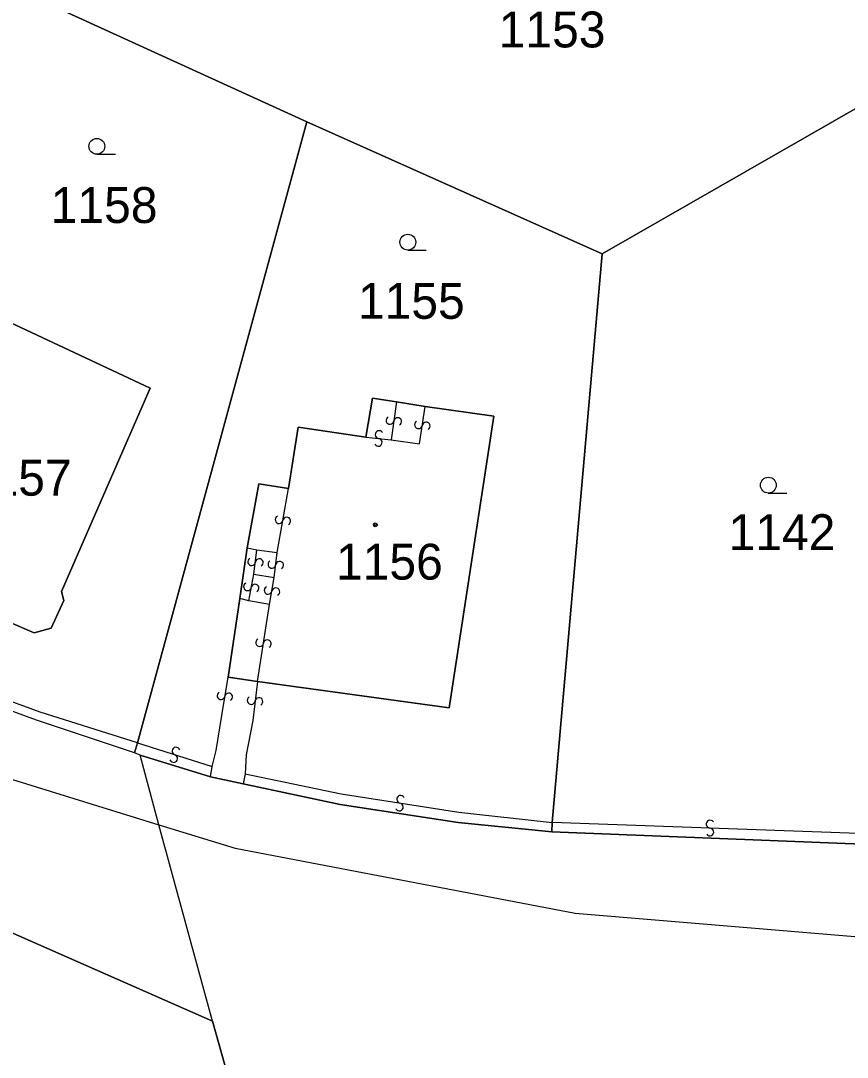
# Model space of a CAD drawing. Extents: x -600309 to -598967, y -1161267 to -1160292.
# Drawn here: x -599956.99 to -599917.86, y -1160621.06 to -1160571.95 of the extents above; entities that cross this region are included whole.
import ezdxf

# ---------------------------------------------------------------- set-up
doc = ezdxf.new("R2010")
doc.units = 0
for name, color, linetype in [('Level 1', 7, 'Continuous'), ('Level 13', 7, 'Continuous'), ('Level 3', 7, 'Continuous'), ('Level 4', 7, 'Continuous'), ('Level 5', 7, 'Continuous'), ('Level 60', 7, 'Continuous'), ('Vrstva 60', 7, 'Continuous')]:
    doc.layers.add(name, color=color, linetype=linetype)

msp = doc.modelspace()

# ---------------------------------------------------------------- linework, layer by layer
at = {"layer": 'Level 1'}
for points in [[(-599947.92, -1160619.35), (-599967.59, -1160610.68), (-599967.72, -1160610.62), (-599986.75, -1160601.72), (-600000.45, -1160595.4), (-600016.14, -1160587.57), (-600029.82, -1160579.77), (-600047.03, -1160569.17)], [(-599943.45, -1160576.74), (-599956.77, -1160570.64)], [(-599929.47, -1160582.99), (-599910.35, -1160572.03)], [(-599951.47, -1160606.16), (-599943.45, -1160576.74)], [(-599929.47, -1160582.99), (-599943.45, -1160576.74)], [(-599931.84, -1160609.93), (-599929.47, -1160582.99)], [(-599964.88, -1160596.05), (-599964.47, -1160595.25), (-599964, -1160595.17), (-599962.35, -1160591.23), (-599962.87, -1160591), (-599961.13, -1160587.24), (-599960.62, -1160587.42), (-599959.57, -1160585.28), (-599950.87, -1160589.35), (-599955.07, -1160598.99), (-599954.95, -1160599.42), (-599955.55, -1160600.73), (-599956.36, -1160600.95), (-599957.61, -1160600.42), (-599957.75, -1160599.84), (-599962.84, -1160597.43), (-599963.36, -1160597.66), (-599964.53, -1160597.13), (-599964.88, -1160596.05)], [(-599937.85, -1160590.23), (-599934.59, -1160590.69), (-599936.71, -1160604.5), (-599945.78, -1160603.26)], [(-599940.65, -1160591.67), (-599940.34, -1160589.83), (-599939.2, -1160590.01)], [(-599939.2, -1160590.01), (-599937.85, -1160590.23)], [(-599944.32, -1160594.11), (-599943.86, -1160591.21), (-599940.65, -1160591.67)], [(-599946.27, -1160596.92), (-599945.72, -1160593.89), (-599944.32, -1160594.11)], [(-599946.62, -1160599.32), (-599946.27, -1160596.92)], [(-599951.61, -1160606.63), (-599956.25, -1160605.09), (-599963.19, -1160602.54), (-599967.54, -1160600.81), (-599970.27, -1160599.54)], [(-599947.18, -1160603.05), (-599946.62, -1160599.32)], [(-599945.78, -1160603.26), (-599947.18, -1160603.05)], [(-599951.61, -1160606.63), (-599951.47, -1160606.16)], [(-599951.34, -1160606.74), (-599951.61, -1160606.63)], [(-599948.01, -1160607.77), (-599951.34, -1160606.74)], [(-599950.45, -1160610.04), (-599951.34, -1160606.74)], [(-599946.46, -1160608.11), (-599948.01, -1160607.77)], [(-599931.85, -1160610.38), (-599936.28, -1160609.94), (-599941.87, -1160609.09), (-599946.46, -1160608.11)], [(-599947.92, -1160619.35), (-599950.45, -1160610.04)], [(-599931.85, -1160610.38), (-599931.84, -1160609.93)], [(-599916.36, -1160611), (-599931.85, -1160610.38)], [(-599945.69, -1160627.27), (-599947.92, -1160619.35), (-599967.59, -1160610.68)], [(-599822.46, -1160624.97), (-599824.85, -1160625.23), (-599827.9, -1160625.24), (-599856.9, -1160625.7), (-599897.68, -1160626.45), (-599908.66, -1160626.66), (-599911.59, -1160626.72), (-599913.75, -1160626.78), (-599917.47, -1160626.86), (-599931.02, -1160627.04), (-599938.13, -1160627.17), (-599938.52, -1160627.22), (-599945.69, -1160627.27), (-599947.92, -1160619.35)]]:
    msp.add_lwpolyline(points, dxfattribs=at)
at = {"layer": 'Level 13'}
for centre, start, end in [((-599939.512, -1160590.883), 118.9391, 351.5291), ((-599939.148, -1160590.938), 299.1535, 171.2515), ((-599938.162, -1160591.091), 118.6996, 350.7976), ((-599937.798, -1160591.149), 298.4851, 171.0751), ((-599940.027, -1160591.557), 30.6629, 262.7609), ((-599940.072, -1160591.923), 210.4484, 83.0384), ((-599944.761, -1160595.587), 117.4511, 349.5491), ((-599944.399, -1160595.653), 297.2366, 169.8266), ((-599946.063, -1160597.574), 119.9413, 352.0393), ((-599945.698, -1160597.625), 299.7269, 172.3169), ((-599945.103, -1160597.707), 120.6066, 352.7046), ((-599944.737, -1160597.752), 300.3921, 172.9821), ((-599946.261, -1160598.764), 116.6714, 348.7694), ((-599945.899, -1160598.835), 296.4569, 169.0469), ((-599945.281, -1160598.936), 117.2634, 349.3614), ((-599944.919, -1160599.003), 297.049, 169.639), ((-599945.682, -1160601.41), 118.6502, 350.7482), ((-599945.318, -1160601.469), 298.4357, 171.0257), ((-599947.512, -1160603.928), 118.0125, 350.1105), ((-599947.149, -1160603.991), 297.7981, 170.3881), ((-599946.083, -1160604.156), 120.0333, 352.6233), ((-599945.717, -1160604.205), 300.2477, 172.3457), ((-599949.642, -1160606.555), 19.6692, 251.7672), ((-599949.757, -1160606.905), 199.4547, 72.0447), ((-599939.01, -1160608.838), 28.5109, 260.6089), ((-599939.069, -1160609.202), 208.2964, 80.8864), ((-599924.353, -1160610.016), 35.091, 267.681), ((-599924.368, -1160610.384), 215.3055, 87.4035)]:
    msp.add_arc(centre, 0.184, start, end, dxfattribs=at)
at = {"layer": 'Level 3'}
for points in [[(-599939.2, -1160590.01), (-599939.46, -1160591.81)], [(-599939.46, -1160591.81), (-599938.12, -1160592), (-599937.85, -1160590.23)], [(-599940.65, -1160591.67), (-599939.46, -1160591.81)], [(-599944.85, -1160597.14), (-599944.32, -1160594.11)], [(-599946.27, -1160596.92), (-599945.81, -1160597.02)], [(-599945.96, -1160598.17), (-599945.81, -1160597.02)], [(-599945.81, -1160597.02), (-599944.85, -1160597.14)], [(-599944.99, -1160598.32), (-599944.85, -1160597.14)], [(-599946.2, -1160599.44), (-599945.96, -1160598.17)], [(-599945.96, -1160598.17), (-599944.99, -1160598.32)], [(-599945.22, -1160599.61), (-599944.99, -1160598.32)], [(-599971.98, -1160598.78), (-599972.33, -1160600.33), (-599972.26, -1160600.47), (-599970.43, -1160602.57), (-599964.27, -1160605.31), (-599957.39, -1160607.9), (-599950.45, -1160610.04)], [(-599946.2, -1160599.44), (-599946.62, -1160599.32)], [(-599945.22, -1160599.61), (-599946.2, -1160599.44)], [(-599945.78, -1160603.26), (-599945.22, -1160599.61)], [(-599951.47, -1160606.16), (-599956.07, -1160604.71), (-599962.94, -1160602.19), (-599967.35, -1160600.36)], [(-599947.93, -1160607.29), (-599947.74, -1160606.52), (-599947.48, -1160604.87), (-599947.18, -1160603.05)], [(-599945.78, -1160603.26), (-599946.01, -1160605.1), (-599946.32, -1160606.73), (-599946.37, -1160607.63)], [(-599951.47, -1160606.16), (-599947.93, -1160607.29)], [(-599948.01, -1160607.77), (-599947.93, -1160607.29)], [(-599916.68, -1160607.42), (-599916.88, -1160610.47), (-599931.84, -1160609.93)], [(-599946.37, -1160607.63), (-599946.46, -1160608.11)], [(-599946.37, -1160607.63), (-599941.83, -1160608.58), (-599936.25, -1160609.45), (-599931.84, -1160609.93)], [(-599950.45, -1160610.04), (-599946.84, -1160611.15), (-599930.75, -1160614.23), (-599910.49, -1160615.93), (-599869.97, -1160617.9), (-599862.37, -1160617.92), (-599827.43, -1160617.28), (-599823.51, -1160617.04)]]:
    msp.add_lwpolyline(points, dxfattribs=at)
at = {"layer": 'Level 5'}
for p, q in [((-599953.39, -1160578.27), (-599952.515, -1160578.27)), ((-599938.67, -1160582.81), (-599937.795, -1160582.81)), ((-599921.6, -1160594.33), (-599920.725, -1160594.33))]:
    msp.add_line(p, q, dxfattribs=at)
for centre, radius in [((-599953.39, -1160577.895), 0.375), ((-599938.67, -1160582.435), 0.375), ((-599921.6, -1160593.955), 0.375), ((-599940.21, -1160595.83), 0.09), ((-599940.21, -1160595.83), 0.0521)]:
    msp.add_circle(centre, radius, dxfattribs=at)
at = {"layer": 'Level 60'}
for points in [[(-599956.77, -1160570.64), (-599943.45, -1160576.74), (-599951.47, -1160606.16), (-599951.61, -1160606.63), (-599956.25, -1160605.09), (-599963.19, -1160602.54), (-599967.54, -1160600.81), (-599970.27, -1160599.54), (-599957.22, -1160570.44), (-599956.95, -1160570.55)], [(-599892.48, -1160611.75), (-599892.58, -1160612.08), (-599914.71, -1160611), (-599916.36, -1160611), (-599931.85, -1160610.38), (-599931.84, -1160609.93), (-599929.47, -1160582.99), (-599910.35, -1160572.03), (-599910.32, -1160572.73), (-599898.47, -1160577.75), (-599890.79, -1160581.05), (-599891.52, -1160594.28), (-599892.32, -1160608.67)], [(-599931.84, -1160609.93), (-599931.85, -1160610.38), (-599936.28, -1160609.94), (-599941.87, -1160609.09), (-599946.46, -1160608.11), (-599948.01, -1160607.77), (-599951.34, -1160606.74), (-599951.61, -1160606.63), (-599951.47, -1160606.16), (-599943.45, -1160576.74), (-599929.47, -1160582.99)], [(-599950.87, -1160589.35), (-599955.07, -1160598.99), (-599954.95, -1160599.42), (-599955.55, -1160600.73), (-599956.36, -1160600.95), (-599957.61, -1160600.42), (-599957.75, -1160599.84), (-599962.84, -1160597.43), (-599963.36, -1160597.66), (-599964.53, -1160597.13), (-599964.88, -1160596.05), (-599964.47, -1160595.25), (-599964, -1160595.17), (-599962.35, -1160591.23), (-599962.87, -1160591), (-599961.13, -1160587.24), (-599960.62, -1160587.42), (-599959.57, -1160585.28)], [(-599955.07, -1160598.99), (-599950.87, -1160589.35), (-599959.57, -1160585.28), (-599960.62, -1160587.42), (-599961.13, -1160587.24), (-599962.87, -1160591), (-599962.35, -1160591.23), (-599964, -1160595.17), (-599964.47, -1160595.25), (-599964.88, -1160596.05), (-599964.53, -1160597.13), (-599963.36, -1160597.66), (-599962.84, -1160597.43), (-599957.75, -1160599.84), (-599957.61, -1160600.42), (-599956.36, -1160600.95), (-599955.55, -1160600.73), (-599954.95, -1160599.42)], [(-599945.78, -1160603.26), (-599947.18, -1160603.05), (-599946.62, -1160599.32), (-599946.27, -1160596.92), (-599945.72, -1160593.89), (-599944.32, -1160594.11), (-599943.86, -1160591.21), (-599940.65, -1160591.67), (-599940.34, -1160589.83), (-599939.2, -1160590.01), (-599937.85, -1160590.23), (-599934.59, -1160590.69), (-599936.71, -1160604.5)], [(-599947.18, -1160603.05), (-599945.78, -1160603.26), (-599936.71, -1160604.5), (-599934.59, -1160590.69), (-599937.85, -1160590.23), (-599939.2, -1160590.01), (-599940.34, -1160589.83), (-599940.65, -1160591.67), (-599943.86, -1160591.21), (-599944.32, -1160594.11), (-599945.72, -1160593.89), (-599946.27, -1160596.92), (-599946.62, -1160599.32)]]:
    msp.add_lwpolyline(points, close=True, dxfattribs=at)
for points in [[(-599910.35, -1160572.03), (-599929.47, -1160582.99), (-599943.45, -1160576.74), (-599956.77, -1160570.64)], [(-599945.69, -1160627.27), (-599947.92, -1160619.35), (-599950.45, -1160610.04), (-599951.34, -1160606.74), (-599948.01, -1160607.77), (-599946.46, -1160608.11), (-599941.87, -1160609.09), (-599936.28, -1160609.94), (-599931.85, -1160610.38), (-599916.36, -1160611), (-599914.71, -1160611), (-599892.58, -1160612.08), (-599892.03, -1160612.17), (-599889.27, -1160612.32), (-599887.41, -1160612.41), (-599885.14, -1160612.52), (-599865.01, -1160613.52), (-599851.49, -1160613.7), (-599824.1, -1160612.62), (-599823.51, -1160617.04), (-599822.46, -1160624.97)], [(-600062.47, -1160615.04), (-600021.97, -1160615.32), (-600020.31, -1160615.48), (-600009.66, -1160615.67), (-599977.16, -1160615.54), (-599968.94, -1160615.73), (-599967.44, -1160615.66), (-599966.83, -1160615.26), (-599966.52, -1160614.75), (-599966.43, -1160614.25), (-599966.79, -1160613.23), (-599967.75, -1160612.71), (-599968.49, -1160612.37), (-599968.15, -1160611.42), (-599967.9, -1160610.95), (-599967.72, -1160610.62), (-599967.59, -1160610.68), (-599947.92, -1160619.35), (-599945.69, -1160627.27)]]:
    msp.add_lwpolyline(points, dxfattribs=at)
at = {"layer": 'Vrstva 60'}
msp.add_lwpolyline([(-600047.03, -1160569.17), (-600029.82, -1160579.77), (-600016.14, -1160587.57), (-600000.45, -1160595.4), (-599986.75, -1160601.72), (-599967.72, -1160610.62), (-599967.59, -1160610.68), (-599947.92, -1160619.35), (-599950.45, -1160610.04), (-599951.34, -1160606.74), (-599951.61, -1160606.63), (-599956.25, -1160605.09), (-599963.19, -1160602.54), (-599967.54, -1160600.81), (-599970.27, -1160599.54), (-599971.98, -1160598.78), (-599977.75, -1160596.26), (-599979.56, -1160595.43), (-600006.69, -1160582.5), (-600006.97, -1160582.28), (-600008.03, -1160581.78), (-600009.08, -1160581.25), (-600017.34, -1160576.84), (-600025.68, -1160571.86)], dxfattribs=at)

# ---------------------------------------------------------------- texts
at = {"layer": 'Level 4'}
for s, p in [('1153', (-599934.366, -1160573.21)), ('1158', (-599955.577, -1160581.53)), ('1155', (-599941.031, -1160586.07)), ('1157', (-599959.644, -1160594.45)), ('1142', (-599923.483, -1160597.03)), ('1156', (-599942.07, -1160598.43))]:
    msp.add_text(s, height=1.7, dxfattribs=at).set_placement(p)

doc.saveas('drawing.dxf')
